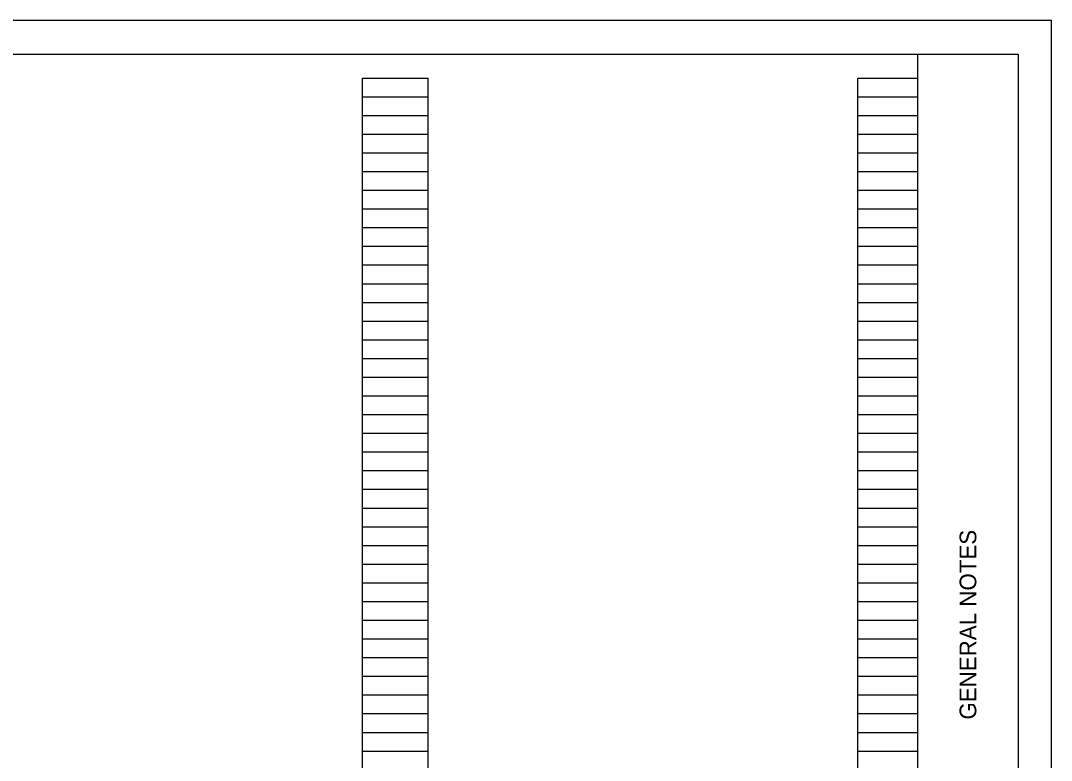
# Model space of a CAD drawing. Extents: x 0 to 37.1, y 0 to 22.
# Drawn here: x 18.56 to 34, y 10.92 to 22 of the extents above; entities that cross this region are included whole.
import ezdxf

# ---------------------------------------------------------------- set-up
doc = ezdxf.new("R2010")
doc.units = 0
for name, color, linetype in [('SH_Border', 7, 'Continuous'), ('SH_Cut_Line', 7, 'Continuous'), ('SH_Data', 7, 'Continuous')]:
    doc.layers.add(name, color=color, linetype=linetype)

msp = doc.modelspace()

# ---------------------------------------------------------------- linework, layer by layer
at = {"layer": 'SH_Border'}
msp.add_line((32, 0.5), (32, 21.5), dxfattribs=at)
msp.add_lwpolyline([(1.5, 21.5), (33.5, 21.5), (33.5, 0.5), (1.5, 0.5)], close=True, dxfattribs=at)
at = {"layer": 'SH_Cut_Line'}
msp.add_lwpolyline([(0, 0), (34, 0), (34, 22), (0, 22)], close=True, dxfattribs=at)
at = {"layer": 'SH_Data'}
for p, q in [((23.68, 0.98), (23.68, 21.14)), ((23.68, 21.14), (24.66, 21.14)), ((24.66, 0.98), (24.66, 21.14)), ((31.1, 0.98), (31.1, 21.14)), ((31.1, 21.14), (32, 21.14)), ((32, 0.98), (32, 21.14)), ((23.68, 20.86), (24.66, 20.86)), ((31.1, 20.86), (32, 20.86)), ((23.68, 20.58), (24.66, 20.58)), ((31.1, 20.58), (32, 20.58)), ((23.68, 20.3), (24.66, 20.3)), ((31.1, 20.3), (32, 20.3)), ((23.68, 20.02), (24.66, 20.02)), ((31.1, 20.02), (32, 20.02)), ((23.68, 19.74), (24.66, 19.74)), ((31.1, 19.74), (32, 19.74)), ((23.68, 19.46), (24.66, 19.46)), ((31.1, 19.46), (32, 19.46)), ((23.68, 19.18), (24.66, 19.18)), ((31.1, 19.18), (32, 19.18)), ((23.68, 18.9), (24.66, 18.9)), ((31.1, 18.9), (32, 18.9)), ((23.68, 18.62), (24.66, 18.62)), ((31.1, 18.62), (32, 18.62)), ((23.68, 18.34), (24.66, 18.34)), ((31.1, 18.34), (32, 18.34)), ((23.68, 18.06), (24.66, 18.06)), ((31.1, 18.06), (32, 18.06)), ((23.68, 17.78), (24.66, 17.78)), ((31.1, 17.78), (32, 17.78)), ((23.68, 17.5), (24.66, 17.5)), ((31.1, 17.5), (32, 17.5)), ((23.68, 17.22), (24.66, 17.22)), ((31.1, 17.22), (32, 17.22)), ((23.68, 16.94), (24.66, 16.94)), ((31.1, 16.94), (32, 16.94)), ((23.68, 16.66), (24.66, 16.66)), ((31.1, 16.66), (32, 16.66)), ((23.68, 16.38), (24.66, 16.38)), ((31.1, 16.38), (32, 16.38)), ((23.68, 16.1), (24.66, 16.1)), ((31.1, 16.1), (32, 16.1)), ((23.68, 15.82), (24.66, 15.82)), ((31.1, 15.82), (32, 15.82)), ((23.68, 15.54), (24.66, 15.54)), ((31.1, 15.54), (32, 15.54)), ((23.68, 15.26), (24.66, 15.26)), ((31.1, 15.26), (32, 15.26)), ((23.68, 14.98), (24.66, 14.98)), ((31.1, 14.98), (32, 14.98)), ((23.68, 14.7), (24.66, 14.7)), ((31.1, 14.7), (32, 14.7)), ((23.68, 14.42), (24.66, 14.42)), ((31.1, 14.42), (32, 14.42)), ((23.68, 14.14), (24.66, 14.14)), ((31.1, 14.14), (32, 14.14)), ((23.68, 13.86), (24.66, 13.86)), ((31.1, 13.86), (32, 13.86)), ((23.68, 13.58), (24.66, 13.58)), ((31.1, 13.58), (32, 13.58)), ((23.68, 13.3), (24.66, 13.3)), ((31.1, 13.3), (32, 13.3)), ((23.68, 13.02), (24.66, 13.02)), ((31.1, 13.02), (32, 13.02)), ((23.68, 12.74), (24.66, 12.74)), ((31.1, 12.74), (32, 12.74)), ((23.68, 12.46), (24.66, 12.46)), ((31.1, 12.46), (32, 12.46)), ((23.68, 12.18), (24.66, 12.18)), ((31.1, 12.18), (32, 12.18)), ((23.68, 11.9), (24.66, 11.9)), ((31.1, 11.9), (32, 11.9)), ((23.68, 11.62), (24.66, 11.62)), ((31.1, 11.62), (32, 11.62)), ((23.68, 11.34), (24.66, 11.34)), ((31.1, 11.34), (32, 11.34)), ((23.68, 11.06), (24.66, 11.06)), ((31.1, 11.06), (32, 11.06))]:
    msp.add_line(p, q, dxfattribs=at)

# ---------------------------------------------------------------- texts
msp.add_text('GENERAL NOTES', height=0.25, rotation=90, dxfattribs=at).set_placement((32.875, 11.531))

doc.saveas('drawing.dxf')
